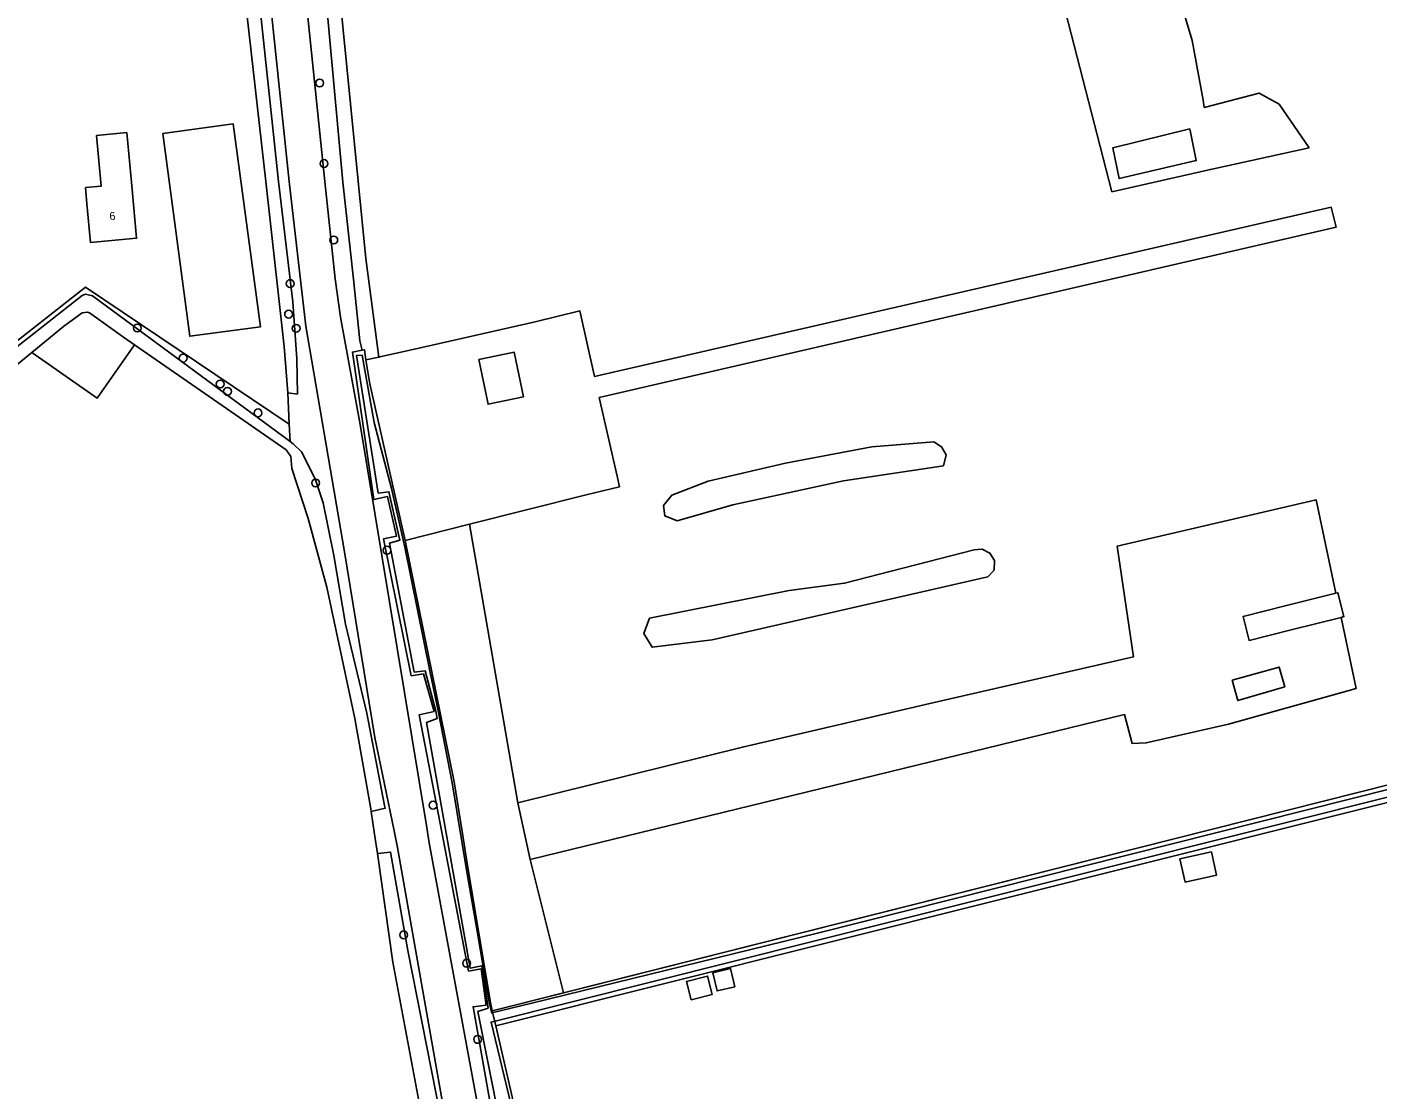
# Model space of a CAD drawing. Extents: x 163863 to 164644, y 379566 to 382155.
# Drawn here: x 164337.9 to 164506.5, y 381886.6 to 382019.3 of the extents above; entities that cross this region are included whole.
import ezdxf

# ---------------------------------------------------------------- set-up
doc = ezdxf.new("R2010")
doc.units = 0
for name, color, linetype in [('IMGEO_Boom', 7, 'Continuous'), ('IMGEO_Erf', 7, 'Continuous'), ('IMGEO_Grasland_agrarisch', 7, 'Continuous'), ('IMGEO_Grasland_overig', 7, 'Continuous'), ('IMGEO_Groenvoorziening', 7, 'Continuous'), ('IMGEO_Hek', 7, 'Continuous'), ('IMGEO_Pand', 7, 'Continuous'), ('IMGEO_Pand_nummerreeks', 7, 'Continuous'), ('IMGEO_Rijbaan_lokaal_halfverhard', 7, 'Continuous'), ('IMGEO_Waterloop', 7, 'Continuous')]:
    doc.layers.add(name, color=color, linetype=linetype)

msp = doc.modelspace()

# ---------------------------------------------------------------- linework, layer by layer
at = {"layer": 'IMGEO_Boom'}
for centre in [(164374.41, 382012.3), (164374.96, 382002.25), (164376.17, 381992.7), (164370.72, 381987.26), (164370.53, 381983.44), (164351.64, 381981.71), (164371.47, 381981.67), (164357.36, 381977.96), (164361.99, 381974.72), (164362.89, 381973.8), (164366.71, 381971.12), (164373.92, 381962.37), (164382.82, 381953.97), (164388.58, 381922.14), (164384.9, 381905.95), (164392.78, 381902.41), (164394.15, 381892.9)]:
    msp.add_circle(centre, 0.489, dxfattribs=at)
at = {"layer": 'IMGEO_Erf'}
msp.add_lwpolyline([(164385.1, 381955.18), (164380.67, 381974.75), (164380.2, 381977.73)], dxfattribs=at)
at = {"layer": 'IMGEO_Grasland_agrarisch'}
for points in [[(164381.79, 381978.08), (164381.92, 381978.11), (164386.24, 381979.09), (164401.35, 381982.49), (164406.92, 381983.84), (164408.76, 381975.66), (164500.79, 381996.8), (164501.4, 381994.3), (164409.35, 381973.02), (164411.56, 381963.21), (164411.86, 381961.89), (164407.72, 381960.9), (164393.11, 381957.21)], [(164338.46, 381978.67), (164346.62, 381972.97), (164351.27, 381979.63)], [(164399.15, 381922.42), (164427.22, 381929.39), (164450.64, 381934.85), (164476.09, 381940.68), (164474.03, 381954.47), (164498.89, 381960.27), (164501.37, 381948.61)], [(164404.87, 381898.71), (164500, 381922.69), (164597.99, 381947.39)], [(164502.01, 381945.59), (164503.9, 381936.71), (164487.97, 381932.24), (164477.68, 381929.91), (164475.9, 381929.85), (164474.95, 381933.46), (164400.69, 381915.35)], [(164380.84, 381921.34), (164381.27, 381918.53), (164381.64, 381916.11)]]:
    msp.add_lwpolyline(points, dxfattribs=at)
at = {"layer": 'IMGEO_Grasland_overig'}
for points in [[(164369.59, 382090.41), (164371.92, 382069.69), (164374.73, 382046.33), (164377.32, 382019.35), (164380.2, 381990.41), (164381.79, 381978.08)], [(164374.69, 382027.13), (164374.98, 382025.23), (164375, 382024.99), (164377.32, 381999.91), (164378.62, 381987.8), (164379.45, 381980.13), (164379.72, 381978.95)], [(164498.03, 382004.23), (164485.7, 382001.51), (164473.39, 381998.73), (164467.22, 382022.66), (164467.02, 382023.39), (164479.26, 382026.66), (164481.61, 382023.65), (164483.42, 382017.63), (164484.77, 382010.15), (164484.92, 382009.26), (164491.77, 382011.05), (164494.28, 382009.65), (164498.03, 382004.23)], [(164302.43, 381952.58), (164302.08, 381953.03), (164345.16, 381986.83), (164370.62, 381969.69)], [(164380.2, 381977.73), (164380, 381979), (164379.72, 381978.95)], [(164380.2, 381977.73), (164381.79, 381978.08)], [(164370.62, 381969.69), (164370.71, 381967.54)], [(164452.33, 381964.52), (164439.86, 381962.63), (164426.02, 381959.64), (164419.08, 381957.64), (164417.53, 381958.25), (164417.36, 381959.54), (164418.39, 381960.86), (164422.95, 381962.59), (164432.59, 381964.83), (164443.41, 381966.87), (164451.15, 381967.52), (164452.09, 381966.88), (164452.7, 381965.87), (164452.33, 381964.52)], [(164393.11, 381957.21), (164385.1, 381955.18)], [(164393.11, 381957.21), (164399.15, 381922.42)], [(164404.87, 381898.71), (164398.12, 381897.01), (164395.98, 381896.47), (164395.74, 381897.51), (164394.3, 381906.15), (164392.84, 381914.85), (164392.24, 381918.62), (164391.22, 381925.04), (164385.1, 381955.18)], [(164458.67, 381951.48), (164457.88, 381950.64), (164423.44, 381942.8), (164415.95, 381941.86), (164414.92, 381943.57), (164415.61, 381945.49), (164433.06, 381948.93), (164439.98, 381949.85), (164456.16, 381954.02), (164457.18, 381954.11), (164458.15, 381953.62), (164458.7, 381952.7), (164458.67, 381951.48)], [(164399.15, 381922.42), (164400.69, 381915.35)], [(164400.69, 381915.35), (164404.87, 381898.71)]]:
    msp.add_lwpolyline(points, dxfattribs=at)
at = {"layer": 'IMGEO_Groenvoorziening'}
for points in [[(164379.72, 381978.95), (164378.51, 381978.71), (164381.18, 381960.3), (164382.9, 381960.67), (164384, 381955.72), (164382.4, 381955.4), (164385.86, 381938.31), (164387.38, 381938.54), (164388.7, 381933.84), (164386.85, 381933.44), (164389.46, 381919.87), (164393.01, 381901.42), (164394.58, 381901.69), (164395.23, 381897.19), (164393.58, 381896.98), (164396.26, 381881.9)], [(164370.45, 381973.61), (164370.62, 381969.69)], [(164598.04, 381945.02), (164500, 381920.51), (164396.41, 381894.6), (164400.28, 381877.79), (164404.82, 381857.96), (164412.31, 381825.45)]]:
    msp.add_lwpolyline(points, dxfattribs=at)
at = {"layer": 'IMGEO_Hek'}
for points in [[(164302.08, 381953.03), (164345.16, 381986.83), (164370.62, 381969.69)], [(164385.1, 381955.18), (164380.67, 381974.75)], [(164385.1, 381955.18), (164391.22, 381925.04), (164392.24, 381918.62)], [(164395.98, 381896.47), (164398.12, 381897.01), (164500, 381922.69), (164597.99, 381947.39)], [(164598.04, 381945.02), (164500, 381920.51), (164396.41, 381894.6)], [(164392.24, 381918.62), (164392.84, 381914.85)], [(164395.74, 381897.51), (164394.3, 381906.15), (164392.84, 381914.85)], [(164395.98, 381896.47), (164395.74, 381897.51)], [(164396.41, 381894.6), (164395.98, 381896.47)], [(164412.31, 381825.45), (164404.82, 381857.96), (164400.28, 381877.79), (164396.41, 381894.6)]]:
    msp.add_lwpolyline(points, dxfattribs=at)
at = {"layer": 'IMGEO_Pand'}
for points in [[(164354.81, 382006.01), (164363.62, 382007.19), (164367.01, 381981.86), (164358.19, 381980.68), (164354.81, 382006.01)], [(164346.52, 382005.77), (164350.31, 382006.12), (164350.93, 381999.46), (164351.54, 381992.92), (164345.79, 381992.39), (164345.34, 381997.23), (164345.16, 381999.24), (164347.11, 381999.42), (164346.52, 382005.77)], [(164483.1, 382006.59), (164473.5, 382004.19), (164474.29, 382000.37), (164483.93, 382002.61), (164483.1, 382006.59)], [(164394.3, 381977.79), (164395.45, 381972.2), (164399.87, 381973.11), (164398.73, 381978.69), (164394.3, 381977.79)], [(164501.37, 381948.61), (164495.04, 381947.03), (164489.77, 381945.71), (164490.52, 381942.71), (164495.78, 381944.03), (164502.01, 381945.59)], [(164501.37, 381948.61), (164501.62, 381948.67), (164502.36, 381945.68), (164502.01, 381945.59)], [(164488.39, 381937.75), (164489.1, 381935.21), (164494.98, 381936.93), (164494.3, 381939.39), (164488.39, 381937.75)], [(164482.52, 381912.54), (164481.88, 381915.45), (164485.81, 381916.31), (164486.45, 381913.4), (164482.52, 381912.54)], [(164426.27, 381899.47), (164424.07, 381898.96), (164423.54, 381901.23), (164425.74, 381901.74), (164426.27, 381899.47)], [(164420.84, 381897.86), (164420.26, 381900.14), (164422.87, 381900.8), (164423.45, 381898.52), (164420.84, 381897.86)]]:
    msp.add_lwpolyline(points, dxfattribs=at)
at = {"layer": 'IMGEO_Rijbaan_lokaal_halfverhard'}
for points in [[(164394.68, 381881.88), (164388.1, 381917.44), (164387.74, 381919.59), (164379.47, 381969.66), (164377.03, 381983.08), (164376.33, 381987.84), (164375.07, 382000), (164368.33, 382065.24), (164366.23, 382081.36), (164364.66, 382091.74), (164362.19, 382105.09)], [(164360.43, 382089.08), (164361.43, 382082.09), (164365.91, 382044.84), (164370.62, 382000), (164372.7, 381981.96), (164377.52, 381953.78), (164381.31, 381930.61), (164383.71, 381918.93), (164384.14, 381916.84), (164390.52, 381880.76)]]:
    msp.add_lwpolyline(points, dxfattribs=at)
at = {"layer": 'IMGEO_Waterloop'}
for points in [[(164359.75, 382083.3), (164360.54, 382083.2), (164363.01, 382063.74), (164364.97, 382044.42), (164366.37, 382027.45), (164369.27, 382000), (164371.04, 381984.97), (164371.58, 381977.88), (164371.64, 381973.47), (164370.45, 381973.61)], [(164370.45, 381973.61), (164369.98, 381979.41), (164367.67, 382000), (164365.06, 382023.24)], [(164370.71, 381967.54), (164346.03, 381985.72), (164345.16, 381985.92), (164344.76, 381985.77), (164302.43, 381952.58)], [(164351.27, 381979.63), (164349.9, 381980.57), (164345.65, 381983.6), (164345.39, 381983.71), (164344.76, 381983.62), (164342.39, 381981.91), (164338.46, 381978.67)], [(164266.94, 381922.74), (164303.65, 381951.33), (164308.86, 381955.55), (164317.22, 381961.8), (164326.77, 381969.48), (164335.15, 381975.96), (164338.46, 381978.67)], [(164351.27, 381979.63), (164361.16, 381972.8), (164370.21, 381966.51), (164370.79, 381965.67), (164370.92, 381964.17), (164372.99, 381957.95), (164375.29, 381949.34), (164378.81, 381932.98), (164380.79, 381921.68), (164380.84, 381921.34)], [(164398.26, 381875.88), (164394.19, 381896.39), (164395.46, 381896.81), (164394.68, 381902.1), (164393.21, 381901.8), (164387.75, 381932.48), (164389.09, 381932.95), (164388.94, 381933.87), (164387.58, 381938.93), (164386.23, 381938.73), (164383.15, 381954.87), (164384.42, 381955.21), (164383.06, 381961.28), (164381.74, 381961.11), (164379.01, 381978.27), (164379.71, 381978.33), (164381.21, 381969.92), (164383.38, 381961.66), (164385.06, 381954.36), (164388.16, 381938.91), (164389.26, 381933.7), (164390.96, 381924.95), (164392.83, 381913.56), (164394.08, 381906.41), (164395.58, 381897.61), (164395.88, 381896.29), (164395.9, 381896.21), (164400.92, 381897.42), (164436.61, 381906.17), (164597.14, 381946.58)], [(164370.71, 381967.54), (164371.12, 381967.24), (164372.16, 381966.25), (164373.87, 381962.9), (164374.84, 381959.88), (164376.2, 381953.33), (164377.66, 381944.75), (164380.3, 381933.65), (164382.52, 381922.1), (164382.6, 381921.75), (164380.84, 381921.34)], [(164597.23, 381945.58), (164395.83, 381895.07), (164402.11, 381868.95)], [(164381.64, 381916.11), (164383.28, 381916.29), (164385.41, 381903.99), (164389.55, 381883.1), (164393.37, 381864.87), (164404.05, 381820.29), (164402.01, 381819.81)], [(164381.64, 381916.11), (164383.56, 381902.54), (164387.32, 381882.58), (164391.12, 381864.73), (164402.01, 381819.81)]]:
    msp.add_lwpolyline(points, dxfattribs=at)

# ---------------------------------------------------------------- texts
at = {"layer": 'IMGEO_Pand_nummerreeks'}
msp.add_text('6', height=1, rotation=4.7097, dxfattribs=at).set_placement((164348.19, 381995.17))

doc.saveas('drawing.dxf')
